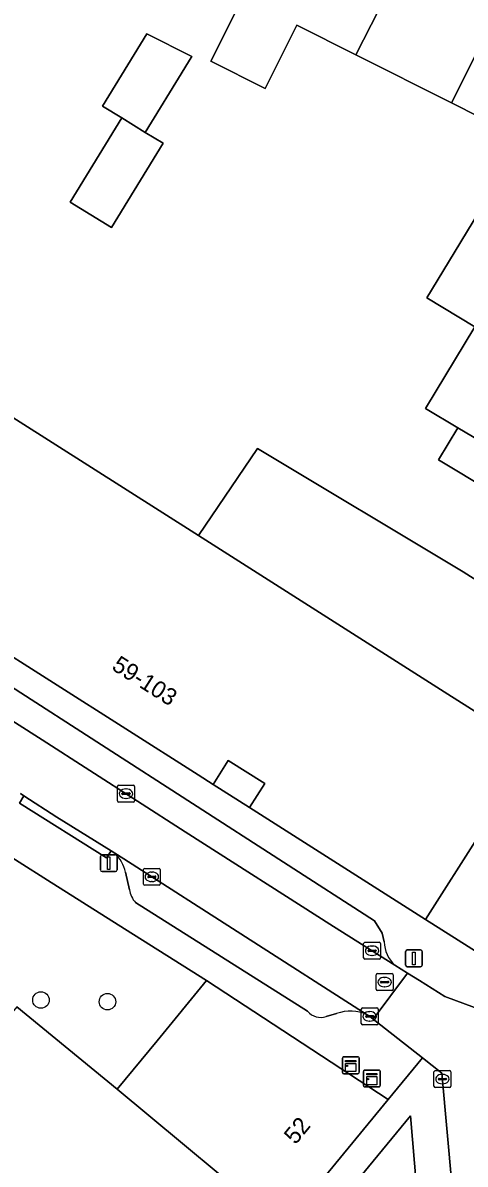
# Model space of a CAD drawing. Extents: x 160663 to 161506, y 382245 to 383291.
# Drawn here: x 161038 to 161064.2, y 383010 to 383077.6 of the extents above; entities that cross this region are included whole.
import ezdxf

# ---------------------------------------------------------------- set-up
doc = ezdxf.new("R2010")
doc.units = 0
for name, color, linetype in [('IMGEO_Boom', 7, 'Continuous'), ('IMGEO_Erf', 7, 'Continuous'), ('IMGEO_Groenvoorziening', 7, 'Continuous'), ('IMGEO_Kast', 7, 'Continuous'), ('IMGEO_Kolk', 7, 'Continuous'), ('IMGEO_Lichtmast', 7, 'Continuous'), ('IMGEO_Muur', 7, 'Continuous'), ('IMGEO_Pand', 7, 'Continuous'), ('IMGEO_Pand_nummerreeks', 7, 'Continuous'), ('IMGEO_Pand_overbouw', 7, 'Continuous'), ('IMGEO_Parkeervlak_open', 7, 'Continuous'), ('IMGEO_Rijbaan_lokaal_open', 7, 'Continuous'), ('IMGEO_Rioolput', 7, 'Continuous'), ('IMGEO_Voetpad_open', 7, 'Continuous'), ('IMGEO_Woonerf_open', 7, 'Continuous')]:
    doc.layers.add(name, color=color, linetype=linetype)

msp = doc.modelspace()

# ---------------------------------------------------------------- linework, layer by layer
at = {"layer": 'IMGEO_Boom'}
for centre in [(161039.102, 383019.684), (161043.043, 383019.585)]:
    msp.add_circle(centre, 0.489, dxfattribs=at)
at = {"layer": 'IMGEO_Erf'}
for points in [[(161066.818, 383071.176), (161063.435, 383072.88), (161057.763, 383075.737), (161054.264, 383077.499), (161052.381, 383073.735), (161049.17, 383075.353), (161051.052, 383079.117)], [(161065.782, 383049.832), (161062.647, 383051.724), (161063.794, 383053.623), (161061.88, 383054.754), (161064.808, 383059.605), (161061.968, 383061.319), (161063.581, 383063.993), (161065.107, 383066.514)], [(161033.411, 383056.782), (161048.444, 383047.224), (161051.939, 383052.395), (161064.119, 383045.068), (161066.763, 383043.403)], [(161037.672, 383019.283), (161043.618, 383014.393), (161045.979, 383017.263), (161048.921, 383020.84), (161043.678, 383024.149), (161039.5, 383026.785), (161036.108, 383028.925)]]:
    msp.add_lwpolyline(points, dxfattribs=at)
for points in [[(161045.384, 383076.974), (161048.036, 383075.639), (161047.906, 383075.427), (161047.625, 383074.969), (161045.276, 383071.139), (161046.337, 383070.488), (161043.275, 383065.494), (161040.826, 383066.996), (161043.889, 383071.99), (161042.754, 383072.686)], [(161049.305, 383032.471), (161051.456, 383031.102), (161052.358, 383032.519), (161050.201, 383033.88)]]:
    msp.add_lwpolyline(points, close=True, dxfattribs=at)
at = {"layer": 'IMGEO_Groenvoorziening'}
msp.add_lwpolyline([(161061.476, 383007.21), (161061.005, 383012.821), (161055.845, 383006.558)], close=True, dxfattribs=at)
at = {"layer": 'IMGEO_Kast'}
for p, q in [((161056.959, 383015.39), (161056.959, 383016.231)), ((161056.959, 383016.231), (161056.959, 383015.39)), ((161057.034, 383016.315), (161057.875, 383016.315)), ((161057.875, 383016.315), (161057.034, 383016.315)), ((161057.959, 383016.24), (161057.959, 383015.399)), ((161057.959, 383015.399), (161057.959, 383016.24)), ((161057.884, 383015.315), (161057.043, 383015.315)), ((161057.043, 383015.315), (161057.884, 383015.315)), ((161058.206, 383014.61), (161058.206, 383015.451)), ((161058.206, 383015.451), (161058.206, 383014.61)), ((161058.281, 383015.535), (161059.122, 383015.535)), ((161059.122, 383015.535), (161058.281, 383015.535)), ((161059.206, 383015.46), (161059.206, 383014.619)), ((161059.206, 383014.619), (161059.206, 383015.46)), ((161059.131, 383014.535), (161058.29, 383014.535)), ((161058.29, 383014.535), (161059.131, 383014.535))]:
    msp.add_line(p, q, dxfattribs=at)
for points in [[(161057.154, 383016.105), (161057.754, 383016.105), (161057.754, 383016.02), (161057.154, 383016.02), (161057.154, 383016.105)], [(161057.154, 383015.93), (161057.754, 383015.93), (161057.754, 383015.441), (161057.154, 383015.441), (161057.154, 383015.93)], [(161058.401, 383015.325), (161059.001, 383015.325), (161059.001, 383015.24), (161058.401, 383015.24), (161058.401, 383015.325)], [(161058.401, 383015.15), (161059.001, 383015.15), (161059.001, 383014.661), (161058.401, 383014.661), (161058.401, 383015.15)]]:
    msp.add_lwpolyline(points, dxfattribs=at)
for centre in [(161057.238, 383015.779), (161058.485, 383014.999)]:
    msp.add_circle(centre, 0.0377, dxfattribs=at)
for centre, start, end in [((161057.037, 383016.237), 92.4484, 184.28452), ((161057.037, 383016.237), 92.4484, 184.28452), ((161057.881, 383016.237), 2.4484, 94.28452), ((161057.881, 383016.237), 2.4484, 94.28452), ((161057.037, 383015.393), 182.4484, 274.28452), ((161057.037, 383015.393), 182.4484, 274.28452), ((161057.881, 383015.393), 272.4484, 4.28452), ((161057.881, 383015.393), 272.4484, 4.28452), ((161058.284, 383015.457), 92.4484, 184.28452), ((161058.284, 383015.457), 92.4484, 184.28452), ((161059.128, 383015.457), 2.4484, 94.28452), ((161059.128, 383015.457), 2.4484, 94.28452), ((161058.284, 383014.613), 182.4484, 274.28452), ((161058.284, 383014.613), 182.4484, 274.28452), ((161059.128, 383014.613), 272.4484, 4.28452), ((161059.128, 383014.613), 272.4484, 4.28452)]:
    msp.add_arc(centre, 0.0779, start, end, dxfattribs=at)
at = {"layer": 'IMGEO_Kolk'}
for p, q in [((161043.64, 383031.496), (161043.64, 383032.348)), ((161043.715, 383032.422), (161044.567, 383032.422)), ((161043.899, 383031.916), (161043.899, 383031.928)), ((161043.942, 383031.965), (161044.34, 383031.965)), ((161044.128, 383032.202), (161044.153, 383032.202)), ((161044.383, 383031.928), (161044.383, 383031.916)), ((161044.641, 383032.348), (161044.641, 383031.496)), ((161044.567, 383031.422), (161043.715, 383031.422)), ((161044.337, 383031.879), (161043.939, 383031.879)), ((161044.151, 383031.642), (161044.126, 383031.642)), ((161045.173, 383026.565), (161045.173, 383027.417)), ((161045.248, 383027.491), (161046.1, 383027.491)), ((161045.661, 383027.271), (161045.686, 383027.271)), ((161046.174, 383027.417), (161046.174, 383026.565)), ((161046.1, 383026.491), (161045.248, 383026.491)), ((161045.432, 383026.985), (161045.432, 383026.997)), ((161045.87, 383026.948), (161045.472, 383026.948)), ((161045.475, 383027.034), (161045.873, 383027.034)), ((161045.684, 383026.711), (161045.659, 383026.711)), ((161045.916, 383026.997), (161045.916, 383026.985)), ((161058.296, 383023.109), (161059.148, 383023.109)), ((161058.221, 383022.183), (161058.221, 383023.035)), ((161058.48, 383022.603), (161058.48, 383022.615)), ((161058.918, 383022.566), (161058.52, 383022.566)), ((161058.523, 383022.652), (161058.921, 383022.652)), ((161058.709, 383022.889), (161058.734, 383022.889)), ((161058.964, 383022.615), (161058.964, 383022.603)), ((161059.222, 383023.035), (161059.222, 383022.183)), ((161059.148, 383022.109), (161058.296, 383022.109)), ((161058.732, 383022.329), (161058.707, 383022.329)), ((161058.082, 383018.29), (161058.082, 383019.142)), ((161058.157, 383019.216), (161059.009, 383019.216)), ((161059.083, 383019.142), (161059.083, 383018.29)), ((161058.341, 383018.71), (161058.341, 383018.722)), ((161058.779, 383018.673), (161058.381, 383018.673)), ((161058.384, 383018.759), (161058.782, 383018.759)), ((161058.593, 383018.436), (161058.568, 383018.436)), ((161058.57, 383018.996), (161058.595, 383018.996)), ((161058.825, 383018.722), (161058.825, 383018.71)), ((161059.009, 383018.216), (161058.157, 383018.216)), ((161062.388, 383014.572), (161062.388, 383015.424)), ((161062.463, 383015.498), (161063.315, 383015.498)), ((161062.647, 383014.992), (161062.647, 383015.004)), ((161062.69, 383015.041), (161063.088, 383015.041)), ((161062.876, 383015.278), (161062.901, 383015.278)), ((161063.131, 383015.004), (161063.131, 383014.992)), ((161063.389, 383015.424), (161063.389, 383014.572)), ((161063.315, 383014.498), (161062.463, 383014.498)), ((161063.085, 383014.955), (161062.687, 383014.955)), ((161062.899, 383014.718), (161062.874, 383014.718))]:
    msp.add_line(p, q, dxfattribs=at)
for points in [[(161043.64, 383031.496), (161043.64, 383032.348)], [(161043.715, 383032.422), (161044.567, 383032.422)], [(161044.641, 383032.348), (161044.641, 383031.496)], [(161044.567, 383031.422), (161043.715, 383031.422)], [(161045.173, 383026.565), (161045.173, 383027.417)], [(161045.248, 383027.491), (161046.1, 383027.491)], [(161046.174, 383027.417), (161046.174, 383026.565)], [(161046.1, 383026.491), (161045.248, 383026.491)], [(161058.296, 383023.109), (161059.148, 383023.109)], [(161058.221, 383022.183), (161058.221, 383023.035)], [(161059.222, 383023.035), (161059.222, 383022.183)], [(161059.148, 383022.109), (161058.296, 383022.109)], [(161058.082, 383018.29), (161058.082, 383019.142)], [(161058.157, 383019.216), (161059.009, 383019.216)], [(161059.083, 383019.142), (161059.083, 383018.29)], [(161059.009, 383018.216), (161058.157, 383018.216)], [(161062.388, 383014.572), (161062.388, 383015.424)], [(161062.463, 383015.498), (161063.315, 383015.498)], [(161063.389, 383015.424), (161063.389, 383014.572)], [(161063.315, 383014.498), (161062.463, 383014.498)]]:
    msp.add_lwpolyline(points, dxfattribs=at)
for centre, radius, start, end in [((161043.717, 383032.346), 0.0765, 91.55205, 178.44795), ((161043.717, 383032.346), 0.0765, 91.55205, 178.44795), ((161043.939, 383031.925), 0.0403, 85.87752, 175.75265), ((161043.936, 383031.915), 0.0366, 178.93798, 274.71019), ((161044.34, 383031.922), 0.043, 264.86636, 352.45326), ((161044.344, 383031.927), 0.0386, 1.73085, 96.63898), ((161044.565, 383032.346), 0.0765, 1.55205, 88.44795), ((161044.565, 383032.346), 0.0765, 1.55205, 88.44795), ((161043.717, 383031.498), 0.0765, 181.55205, 268.44795), ((161043.717, 383031.498), 0.0765, 181.55205, 268.44795), ((161044.565, 383031.498), 0.0765, 271.55205, 358.44795), ((161044.565, 383031.498), 0.0765, 271.55205, 358.44795), ((161045.25, 383027.415), 0.0765, 91.55205, 178.44795), ((161045.25, 383027.415), 0.0765, 91.55205, 178.44795), ((161046.098, 383027.415), 0.0765, 1.55205, 88.44795), ((161046.098, 383027.415), 0.0765, 1.55205, 88.44795), ((161045.25, 383026.567), 0.0765, 181.55205, 268.44795), ((161045.25, 383026.567), 0.0765, 181.55205, 268.44795), ((161045.472, 383026.994), 0.0403, 85.87752, 175.75265), ((161045.469, 383026.984), 0.0366, 178.93798, 274.71019), ((161045.873, 383026.991), 0.043, 264.86636, 352.45326), ((161045.877, 383026.996), 0.0386, 1.73085, 96.63898), ((161046.098, 383026.567), 0.0765, 271.55205, 358.44795), ((161046.098, 383026.567), 0.0765, 271.55205, 358.44795), ((161058.298, 383023.033), 0.0765, 91.55205, 178.44795), ((161058.298, 383023.033), 0.0765, 91.55205, 178.44795), ((161059.146, 383023.033), 0.0765, 1.55205, 88.44795), ((161059.146, 383023.033), 0.0765, 1.55205, 88.44795), ((161058.52, 383022.612), 0.0403, 85.87752, 175.75265), ((161058.517, 383022.602), 0.0366, 178.93798, 274.71019), ((161058.921, 383022.609), 0.043, 264.86636, 352.45326), ((161058.925, 383022.614), 0.0386, 1.73085, 96.63898), ((161058.298, 383022.185), 0.0765, 181.55205, 268.44795), ((161058.298, 383022.185), 0.0765, 181.55205, 268.44795), ((161059.146, 383022.185), 0.0765, 271.55205, 358.44795), ((161059.146, 383022.185), 0.0765, 271.55205, 358.44795), ((161058.159, 383019.14), 0.0765, 91.55205, 178.44795), ((161058.159, 383019.14), 0.0765, 91.55205, 178.44795), ((161059.007, 383019.14), 0.0765, 1.55205, 88.44795), ((161059.007, 383019.14), 0.0765, 1.55205, 88.44795), ((161058.381, 383018.719), 0.0403, 85.87752, 175.75265), ((161058.378, 383018.709), 0.0366, 178.93798, 274.71019), ((161058.782, 383018.716), 0.043, 264.86636, 352.45326), ((161058.786, 383018.721), 0.0386, 1.73085, 96.63898), ((161058.159, 383018.292), 0.0765, 181.55205, 268.44795), ((161058.159, 383018.292), 0.0765, 181.55205, 268.44795), ((161059.007, 383018.292), 0.0765, 271.55205, 358.44795), ((161059.007, 383018.292), 0.0765, 271.55205, 358.44795), ((161062.465, 383015.422), 0.0765, 91.55205, 178.44795), ((161062.465, 383015.422), 0.0765, 91.55205, 178.44795), ((161062.687, 383015.001), 0.0403, 85.87752, 175.75265), ((161062.684, 383014.991), 0.0366, 178.93798, 274.71019), ((161063.088, 383014.998), 0.043, 264.86636, 352.45326), ((161063.092, 383015.003), 0.0386, 1.73085, 96.63898), ((161063.313, 383015.422), 0.0765, 1.55205, 88.44795), ((161063.313, 383015.422), 0.0765, 1.55205, 88.44795), ((161062.465, 383014.574), 0.0765, 181.55205, 268.44795), ((161062.465, 383014.574), 0.0765, 181.55205, 268.44795), ((161063.313, 383014.574), 0.0765, 271.55205, 358.44795), ((161063.313, 383014.574), 0.0765, 271.55205, 358.44795)]:
    msp.add_arc(centre, radius, start, end, dxfattribs=at)
for centre, major_axis, ratio, start_param, end_param in [((161044.127, 383031.922), (-0.387, 0.002), 0.722429, 4.712389, 7.853982), ((161044.152, 383031.922), (-0.39, 0.002), 0.717154, 1.570796, 4.712389), ((161045.66, 383026.991), (-0.387, 0.002), 0.722429, 4.712389, 7.853982), ((161045.685, 383026.991), (-0.39, 0.002), 0.717154, 1.570796, 4.712389), ((161058.708, 383022.609), (-0.387, 0.002), 0.722429, 4.712389, 7.853982), ((161058.733, 383022.609), (-0.39, 0.002), 0.717154, 1.570796, 4.712389), ((161058.569, 383018.716), (-0.387, 0.002), 0.722429, 4.712389, 7.853982), ((161058.594, 383018.716), (-0.39, 0.002), 0.717154, 1.570796, 4.712389), ((161062.875, 383014.998), (-0.387, 0.002), 0.722429, 4.712389, 7.853982), ((161062.9, 383014.998), (-0.39, 0.002), 0.717154, 1.570796, 4.712389)]:
    msp.add_ellipse(centre, major_axis=major_axis, ratio=ratio, start_param=start_param, end_param=end_param, dxfattribs=at)
at = {"layer": 'IMGEO_Lichtmast'}
for p, q in [((161042.623, 383027.398), (161042.623, 383028.198)), ((161042.623, 383028.198), (161042.623, 383027.398)), ((161042.723, 383028.298), (161043.513, 383028.298)), ((161043.513, 383028.298), (161042.723, 383028.298)), ((161043.613, 383028.198), (161043.613, 383027.398)), ((161043.613, 383027.398), (161043.613, 383028.198)), ((161043.513, 383027.298), (161042.723, 383027.298)), ((161042.723, 383027.298), (161043.513, 383027.298)), ((161060.702, 383021.757), (161060.702, 383022.557)), ((161060.702, 383022.557), (161060.702, 383021.757)), ((161060.802, 383022.657), (161061.592, 383022.657)), ((161061.592, 383022.657), (161060.802, 383022.657)), ((161061.692, 383022.557), (161061.692, 383021.757)), ((161061.692, 383021.757), (161061.692, 383022.557)), ((161061.592, 383021.657), (161060.802, 383021.657)), ((161060.802, 383021.657), (161061.592, 383021.657))]:
    msp.add_line(p, q, dxfattribs=at)
for points in [[(161043.043, 383028.173), (161043.193, 383028.173), (161043.193, 383027.423), (161043.043, 383027.423), (161043.043, 383028.173)], [(161061.122, 383022.532), (161061.272, 383022.532), (161061.272, 383021.782), (161061.122, 383021.782), (161061.122, 383022.532)]]:
    msp.add_lwpolyline(points, dxfattribs=at)
for centre, start, end in [((161042.723, 383028.198), 90, 180), ((161042.723, 383028.198), 90, 180), ((161043.513, 383028.198), 0, 90), ((161043.513, 383028.198), 360, 90), ((161042.723, 383027.398), 180, 270), ((161042.723, 383027.398), 180, 270), ((161043.513, 383027.398), 270, 0), ((161043.513, 383027.398), 270, 0), ((161060.802, 383022.557), 90, 180), ((161060.802, 383022.557), 90, 180), ((161061.592, 383022.557), 0, 90), ((161061.592, 383022.557), 360, 90), ((161060.802, 383021.757), 180, 270), ((161060.802, 383021.757), 180, 270), ((161061.592, 383021.757), 270, 0), ((161061.592, 383021.757), 270, 0)]:
    msp.add_arc(centre, 0.1, start, end, dxfattribs=at)
at = {"layer": 'IMGEO_Muur'}
msp.add_lwpolyline([(161039.5, 383026.785), (161043.678, 383024.149)], dxfattribs=at)
at = {"layer": 'IMGEO_Pand'}
for points in [[(161061.386, 383082.869), (161054.43, 383086.396), (161050.842, 383079.223), (161051.052, 383079.117), (161049.17, 383075.353), (161052.381, 383073.735), (161054.264, 383077.499), (161057.763, 383075.737)], [(161063.435, 383072.88), (161067.006, 383080.02), (161061.386, 383082.869), (161057.763, 383075.737)], [(161072.758, 383077.104), (161067.006, 383080.02), (161063.435, 383072.88), (161066.818, 383071.176), (161066.247, 383070.042), (161068.224, 383069.046), (161068.604, 383068.854), (161069.229, 383070.046)], [(161043.889, 383071.99), (161045.276, 383071.139), (161047.625, 383074.969), (161047.906, 383075.427), (161048.036, 383075.639), (161045.384, 383076.974), (161042.754, 383072.686)], [(161045.276, 383071.139), (161043.889, 383071.99), (161040.826, 383066.996), (161043.275, 383065.494), (161046.337, 383070.488)], [(161077.699, 383057.722), (161078.542, 383059.07), (161072.272, 383062.537), (161067.98, 383064.781), (161066.831, 383065.474), (161065.107, 383066.514), (161063.581, 383063.993), (161061.968, 383061.319), (161064.808, 383059.605), (161070.064, 383056.434), (161070.219, 383056.239), (161083.965, 383047.339), (161086.956, 383052.296)], [(161070.219, 383056.239), (161070.064, 383056.434), (161064.808, 383059.605), (161061.88, 383054.754), (161063.794, 383053.623), (161070.716, 383049.531), (161080.695, 383042.622), (161083.062, 383046.224), (161083.23, 383046.122), (161083.965, 383047.339)], [(161048.444, 383047.224), (161033.411, 383056.782), (161029.664, 383050.891), (161027.134, 383046.913), (161026.98, 383046.672), (161048.411, 383033.039), (161049.305, 383032.471), (161050.201, 383033.88), (161052.358, 383032.519), (161051.456, 383031.102), (161061.89, 383024.465), (161068.328, 383034.587), (161063.216, 383037.832)], [(161070.716, 383049.531), (161063.794, 383053.623), (161062.647, 383051.724), (161065.782, 383049.832), (161065.216, 383048.893), (161068.779, 383046.744), (161067.496, 383044.618), (161073.628, 383040.658), (161077.828, 383037.945), (161078.225, 383038.602), (161078.102, 383038.676), (161080.695, 383042.622)], [(161067.496, 383044.618), (161066.763, 383043.403), (161064.119, 383045.068), (161051.939, 383052.395), (161048.444, 383047.224), (161063.216, 383037.832), (161068.328, 383034.587), (161072.765, 383031.735), (161073.387, 383031.365), (161077.074, 383036.911), (161077.828, 383037.945), (161073.628, 383040.658)], [(161061.89, 383024.465), (161066.34, 383021.634), (161072.449, 383031.238), (161072.765, 383031.735), (161068.328, 383034.587)], [(161053.588, 383006.099), (161053.828, 383006.391), (161053.757, 383006.58), (161059.678, 383013.78), (161048.921, 383020.84), (161045.979, 383017.263), (161043.618, 383014.393)], [(161043.618, 383014.393), (161037.672, 383019.283), (161034.176, 383015.032), (161033.334, 383015.724), (161031.521, 383015.548), (161028.345, 383011.687), (161028.208, 383011.521), (161032.628, 383007.886), (161033.307, 383008.711), (161035.066, 383007.264), (161036.596, 383006.006), (161039.021, 383006.242), (161039.115, 383006.165), (161039.477, 383006.191), (161040.172, 383005.56), (161041.064, 383006.713), (161048.722, 383000.343), (161053.349, 383005.973), (161053.468, 383005.953), (161053.588, 383006.099)]]:
    msp.add_lwpolyline(points, close=True, dxfattribs=at)
at = {"layer": 'IMGEO_Pand_overbouw'}
msp.add_lwpolyline([(161049.305, 383032.471), (161051.456, 383031.102), (161052.358, 383032.519), (161050.201, 383033.88)], close=True, dxfattribs=at)
at = {"layer": 'IMGEO_Parkeervlak_open'}
for points in [[(161013.579, 383053.465), (161013.058, 383053.465), (161012.017, 383053.67), (161017.137, 383049.948), (161023.767, 383045.113), (161030.766, 383040.479), (161039.174, 383035.116), (161047.653, 383029.663), (161056.443, 383024.051), (161060.074, 383021.752)], [(161059.441, 383023.143), (161059.314, 383023.651), (161058.871, 383024.388), (161026.498, 383045.25), (161014.924, 383053.146)], [(161058.437, 383018.811), (161044.007, 383028.061), (161043.475, 383028.393)], [(161044.122, 383027.259), (161044.355, 383026.224)], [(161044.706, 383025.469), (161054.903, 383019.021)], [(161055.994, 383018.716), (161056.616, 383018.88)]]:
    msp.add_lwpolyline(points, dxfattribs=at)
for centre, radius, start, end in [((161041.872, 383026.727), 2.312, 13.3049, 46.10866), ((161045.7, 383026.39), 1.355, 187.03797, 222.82953), ((161061.322, 383023.159), 1.881, 180.49885, 228.4387), ((161057.446, 383016.716), 2.317, 64.67621, 110.98385), ((161055.664, 383019.639), 0.981, 219.09407, 289.66819)]:
    msp.add_arc(centre, radius, start, end, dxfattribs=at)
at = {"layer": 'IMGEO_Rijbaan_lokaal_open'}
msp.add_lwpolyline([(161037.89, 383031.927), (161038.093, 383031.787), (161040.038, 383030.538), (161043.259, 383028.541), (161043.475, 383028.393), (161044.007, 383028.061), (161058.437, 383018.811), (161058.587, 383018.715), (161058.789, 383018.556), (161060.814, 383021.283), (161060.074, 383021.752), (161056.443, 383024.051), (161047.653, 383029.663), (161039.174, 383035.116), (161030.766, 383040.479)], dxfattribs=at)
at = {"layer": 'IMGEO_Rioolput'}
for p, q in [((161058.962, 383020.324), (161058.962, 383021.176)), ((161059.037, 383021.25), (161059.889, 383021.25)), ((161059.963, 383021.176), (161059.963, 383020.324)), ((161059.221, 383020.744), (161059.221, 383020.756)), ((161059.659, 383020.707), (161059.261, 383020.707)), ((161059.264, 383020.793), (161059.662, 383020.793)), ((161059.473, 383020.47), (161059.448, 383020.47)), ((161059.45, 383021.03), (161059.475, 383021.03)), ((161059.705, 383020.756), (161059.705, 383020.744)), ((161059.889, 383020.25), (161059.037, 383020.25))]:
    msp.add_line(p, q, dxfattribs=at)
for points in [[(161058.962, 383020.324), (161058.962, 383021.176)], [(161059.037, 383021.25), (161059.889, 383021.25)], [(161059.963, 383021.176), (161059.963, 383020.324)], [(161059.889, 383020.25), (161059.037, 383020.25)]]:
    msp.add_lwpolyline(points, dxfattribs=at)
for centre, radius, start, end in [((161059.039, 383021.174), 0.0765, 91.55205, 178.44795), ((161059.039, 383021.174), 0.0765, 91.55205, 178.44795), ((161059.887, 383021.174), 0.0765, 1.55205, 88.44795), ((161059.887, 383021.174), 0.0765, 1.55205, 88.44795), ((161059.261, 383020.753), 0.0403, 85.87752, 175.75265), ((161059.258, 383020.743), 0.0366, 178.93798, 274.71019), ((161059.662, 383020.75), 0.043, 264.86636, 352.45326), ((161059.666, 383020.755), 0.0386, 1.73085, 96.63898), ((161059.039, 383020.326), 0.0765, 181.55205, 268.44795), ((161059.039, 383020.326), 0.0765, 181.55205, 268.44795), ((161059.887, 383020.326), 0.0765, 271.55205, 358.44795), ((161059.887, 383020.326), 0.0765, 271.55205, 358.44795)]:
    msp.add_arc(centre, radius, start, end, dxfattribs=at)
for centre, major_axis, ratio, start_param, end_param in [((161059.449, 383020.75), (-0.387, 0.002), 0.722429, 4.712389, 7.853982), ((161059.474, 383020.75), (-0.39, 0.002), 0.717154, 1.570796, 4.712389)]:
    msp.add_ellipse(centre, major_axis=major_axis, ratio=ratio, start_param=start_param, end_param=end_param, dxfattribs=at)
at = {"layer": 'IMGEO_Voetpad_open'}
for points in [[(161060.074, 383021.752), (161060.814, 383021.283), (161061.522, 383020.835), (161063.032, 383019.896), (161064.782, 383019.236), (161066.34, 383021.634), (161061.89, 383024.465), (161051.456, 383031.102), (161049.305, 383032.471), (161048.411, 383033.039), (161026.98, 383046.672), (161027.134, 383046.913), (161025.238, 383048.281), (161017.714, 383053.743), (161011.26, 383058.428)], [(161014.924, 383053.146), (161026.498, 383045.25), (161058.871, 383024.388), (161059.314, 383023.651), (161059.441, 383023.143)], [(161043.475, 383028.393), (161043.259, 383028.541), (161042.993, 383028.118), (161037.827, 383031.364), (161038.093, 383031.787), (161037.89, 383031.927)], [(161036.108, 383028.925), (161039.5, 383026.785), (161043.678, 383024.149), (161048.921, 383020.84), (161059.678, 383013.78), (161061.708, 383016.259), (161058.789, 383018.556), (161058.587, 383018.715), (161058.437, 383018.811)], [(161044.355, 383026.224), (161044.122, 383027.259)], [(161054.903, 383019.021), (161044.706, 383025.469)], [(161056.616, 383018.88), (161055.994, 383018.716)], [(161063.468, 383008.572), (161062.859, 383015.353), (161061.708, 383016.259), (161059.678, 383013.78), (161053.757, 383006.58)]]:
    msp.add_lwpolyline(points, dxfattribs=at)
for points in [[(161038.093, 383031.787), (161037.827, 383031.364), (161042.993, 383028.118), (161043.259, 383028.541), (161040.038, 383030.538)], [(161061.476, 383007.21), (161055.845, 383006.558), (161061.005, 383012.821)]]:
    msp.add_lwpolyline(points, close=True, dxfattribs=at)
for centre, radius, start, end in [((161041.872, 383026.727), 2.312, 13.3049, 46.10866), ((161045.7, 383026.39), 1.355, 187.03797, 222.82953), ((161061.322, 383023.159), 1.881, 180.49885, 228.4387), ((161057.446, 383016.716), 2.317, 64.67621, 110.98385), ((161055.664, 383019.639), 0.981, 219.09407, 289.66819)]:
    msp.add_arc(centre, radius, start, end, dxfattribs=at)
at = {"layer": 'IMGEO_Woonerf_open'}
msp.add_lwpolyline([(161067.943, 383009.691), (161072.199, 383014.962), (161072.068, 383016.448), (161073.465, 383018.514), (161072.55, 383018.238), (161070.229, 383019.78), (161070.041, 383020.586), (161069.177, 383019.217), (161065.76, 383018.867), (161064.782, 383019.236), (161063.032, 383019.896), (161061.522, 383020.835), (161060.814, 383021.283), (161058.789, 383018.556), (161061.708, 383016.259), (161062.859, 383015.353), (161063.468, 383008.572)], dxfattribs=at)

# ---------------------------------------------------------------- texts
at = {"layer": 'IMGEO_Pand_nummerreeks'}
for s, rotation, p in [('59-103', 327.53621, (161043.237, 383039.317)), ('52', 50.56745, (161054.186, 383011.069))]:
    msp.add_text(s, height=1, rotation=rotation, dxfattribs=at).set_placement(p)

doc.saveas('drawing.dxf')
